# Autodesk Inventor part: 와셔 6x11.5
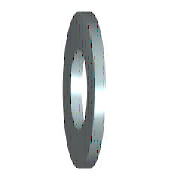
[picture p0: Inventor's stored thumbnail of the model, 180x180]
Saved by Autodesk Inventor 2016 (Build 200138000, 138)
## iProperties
IsCustomPart: 1
Created: 2012-02
Part Number: 와셔 6x11.5
Material: 강철, 연강
Description: 평면 와셔
Document SubType Name: Modeling
Standard: KS B 1326
Designer: mduedu
Standards Organization: KS
Language: ko-KR
Size Designation: 6x11.5
Categories: <MemberInstance><Categories><Category DisplayName="조임쇠" InternalName="e4da775c-781d-43d5-af7c-5136215cf5a6" Mnemonic="FSTN"><Category DisplayName="와셔" InternalN
Density: 1 g/cm^3
Appearance: 주황색
Author: mduedu
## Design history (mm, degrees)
sketch "스케치"
  geometry: C1 r 5.75 at (0, 0); C2 r 3.2 at (0, 0); 1 further point
  constraints: 2 centre point, 2 coincident
  dimensions: "d0" = 6.4 diameter of C2 (= SD1); "d1" = 11.5 diameter of C1 (= SD2)
extrude "본체" new body sketch "스케치" distance "d2" = 1.6 (= SD); taper "d3" = 0 deg
workaxis "Work Axis1"
workplane "Work Plane1"
body "Solid1"
other parameters: "SD1" = 6.4 [user parameter; used in 1 equation term], "SD2" = 11.5 [user parameter; used in 1 equation term], "SD" = 1.6 [user parameter; used in 1 equation term], "d4" = 0, "d5" = 0, "d6" = 0, "d7" = 0, "NND" = 6 [user parameter]
